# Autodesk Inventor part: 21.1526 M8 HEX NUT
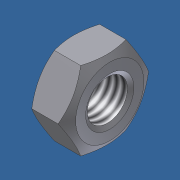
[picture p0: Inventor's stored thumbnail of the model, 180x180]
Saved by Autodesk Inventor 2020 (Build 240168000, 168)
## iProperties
Created: 2006-02
Part Number: 21.1526 M8 HEX NUT
Material: Steel, Mild
Description: M8 HEX NUT
Document SubType Name: Modeling
Standard: DIN 934
Designer: Andy Moles
Standards Organization: DIN
Language: en-US
Size Designation: M8
Categories: <MemberInstance><Categories><Category DisplayName="Fasteners" InternalName="e4da775c-781d-43d5-af7c-5136215cf5a6" Mnemonic="FSTN"><Category DisplayName="Nuts" I
Mass: 5.38065 g
Surface Area: 5.92403 cm^2
Volume: 0.685433 cm^3
Density: 7.85 g/cm^3
Appearance: Zinc
Author: Andy Moles
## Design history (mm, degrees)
sketch "Sketch1"
  geometry: L1 (-7.506, 0)-(-3.753, 6.5); L2 (-3.753, 6.5)-(3.753, 6.5); L3 (3.753, 6.5)-(7.506, 0); L4 (7.506, 0)-(3.753, -6.5); L5 (3.753, -6.5)-(-3.753, -6.5); L6 (-3.753, -6.5)-(-7.506, 0); 2 further points
  constraints: 12 end point, 1 coincident, 1 horizontal, 11 other
  dimensions: "d0" = 15.01111 distance of L3.end L1.start (= 1.1547 x SW)
extrude "Body" new body sketch "Sketch1" distance "d1" = 6.5 (= KOH); taper "d2" = 0 deg
sketch "Sketch2"
  geometry: L1 (0, 3.753)-(0, 7.506) reference; L2 (0, 7.506)-(6.5, 7.506) reference; L3 (6.5, 3.753)-(6.5, 7.506) reference; L4 (-0.65, 0)-(8.45, 0) reference; L5 (1.071, 7.506)-(0, 5.65); L6 (5.429, 7.506)-(6.5, 5.65)
  constraints: 4 end point, 4 point on line
  dimensions: "d3" = 30 deg angle of L1 L5 (= ANG1); "d4" = 30 deg angle of L3 L6 (= ANG2); "d5" = 11.3 diameter of L5.end L4 (= SW0); "d6" = 11.3 diameter of L6.end L4 (= SW01)
revolve "Chamfer1" sketch "Sketch2" stored, may be unused: angle "d7" = 90 deg
sketch "Sketch3"
  geometry: 4 further points
  constraints: 1 coincident, 1 other
hole "Thread" sketch "Sketch3" at (0, 0) diameter "d25" = 6.647; stored, may be unused: countersink angle "d29" = 82 deg, drill point angle "d31" = 118 deg; dims "d26" = 6, "d27" = 4, "d28" = 2, "d30" = 8
workaxis "Work Axis1"
workplane "Work Plane1"
body "Solid1"
chamfer "Chamfer2" distance "d8" = 0.67658 (= -0.5 x GD1 + 0.5 x NND); stored, may be unused: angle "d9" = 30 deg, second distance "d40" = 0.67658 (= -0.5 x GD1 + 0.5 x NND)
chamfer "Chamfer3" distance "d10" = 0.67658 (= -0.5 x GD1 + 0.5 x NND); stored, may be unused: angle "d11" = 30 deg, second distance "d41" = 0.67658 (= -0.5 x GD1 + 0.5 x NND)
other parameters: "ANG1" = 30 deg [user parameter; used in 1 equation term], "ANG2" = 30 deg [user parameter; used in 1 equation term], "NND" = 8 [user parameter; used in 4 equation terms], "KOH" = 6.5 [user parameter; used in 1 equation term], "SW" = 13 [user parameter; used in 2 equation terms], "SW0" = 11.3 (= SW01) [user parameter; used in 1 equation term], "SW01" = 11.3 [user parameter; used in 2 equation terms], "GD1" = 6.64684 (computed from THREADDIA, PTC, TOA) [user parameter; used in 4 equation terms], "d13" = 0, "d14" = 0, "d39" = 0, "d42" = 0, "GUL" = 0.67658 (= 0.541266 x PTC) [user parameter], "TPU" = 8 (computed from PTC) [user parameter], "THREADDIA" = 8 [user parameter; used in 1 equation term], "TOA" = 30 deg [user parameter; used in 1 equation term], "PTC" = 1.25 [user parameter; used in 4 equation terms], "E0" = 15.015 (= 1.155 x SW) [user parameter], "GAL" = 0.67658 (= 0.541266 x PTC) [user parameter]
